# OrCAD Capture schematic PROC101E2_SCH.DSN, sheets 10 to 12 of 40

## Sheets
10 15.EEPROM,PRESENCE DETECT&TEMP: size C; title: EEPROM,PRESENCE DETECTION & TEMP SENSOR
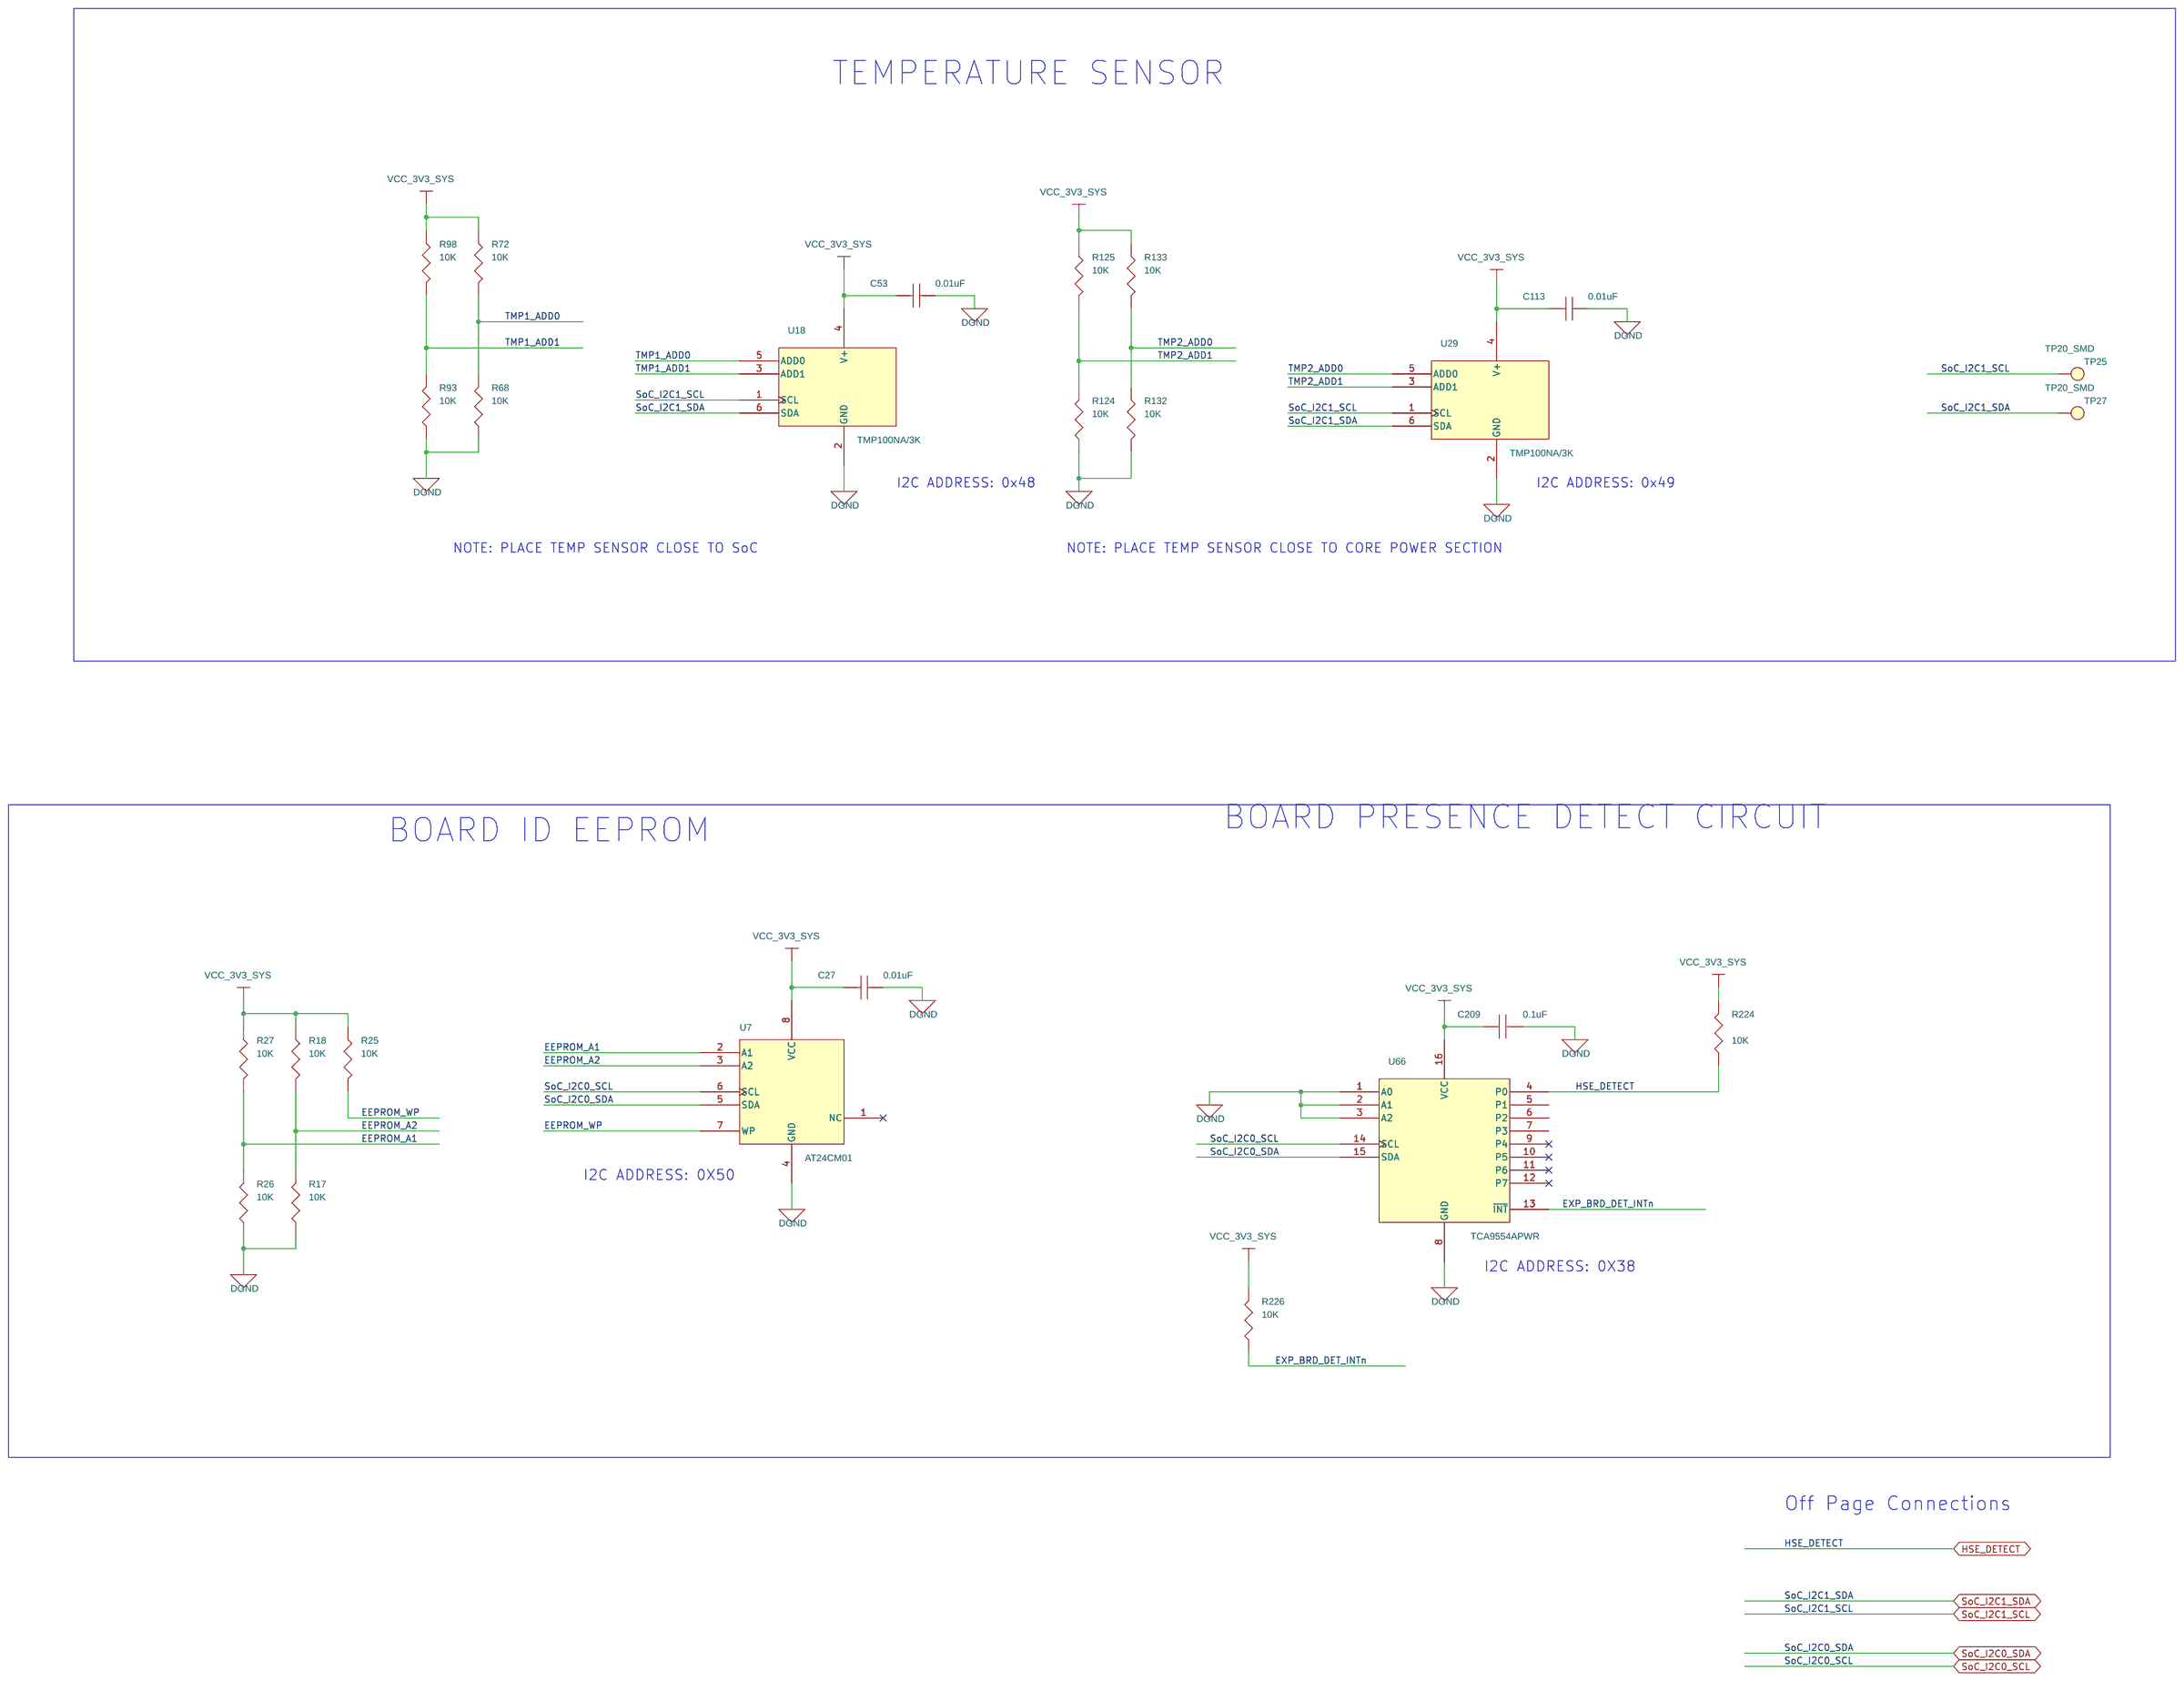
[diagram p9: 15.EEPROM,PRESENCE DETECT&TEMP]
11 31.ETHERNET PHY CLOCK BUFFER: size C; title: ETHERNET PHY CLOCK GENERATOR
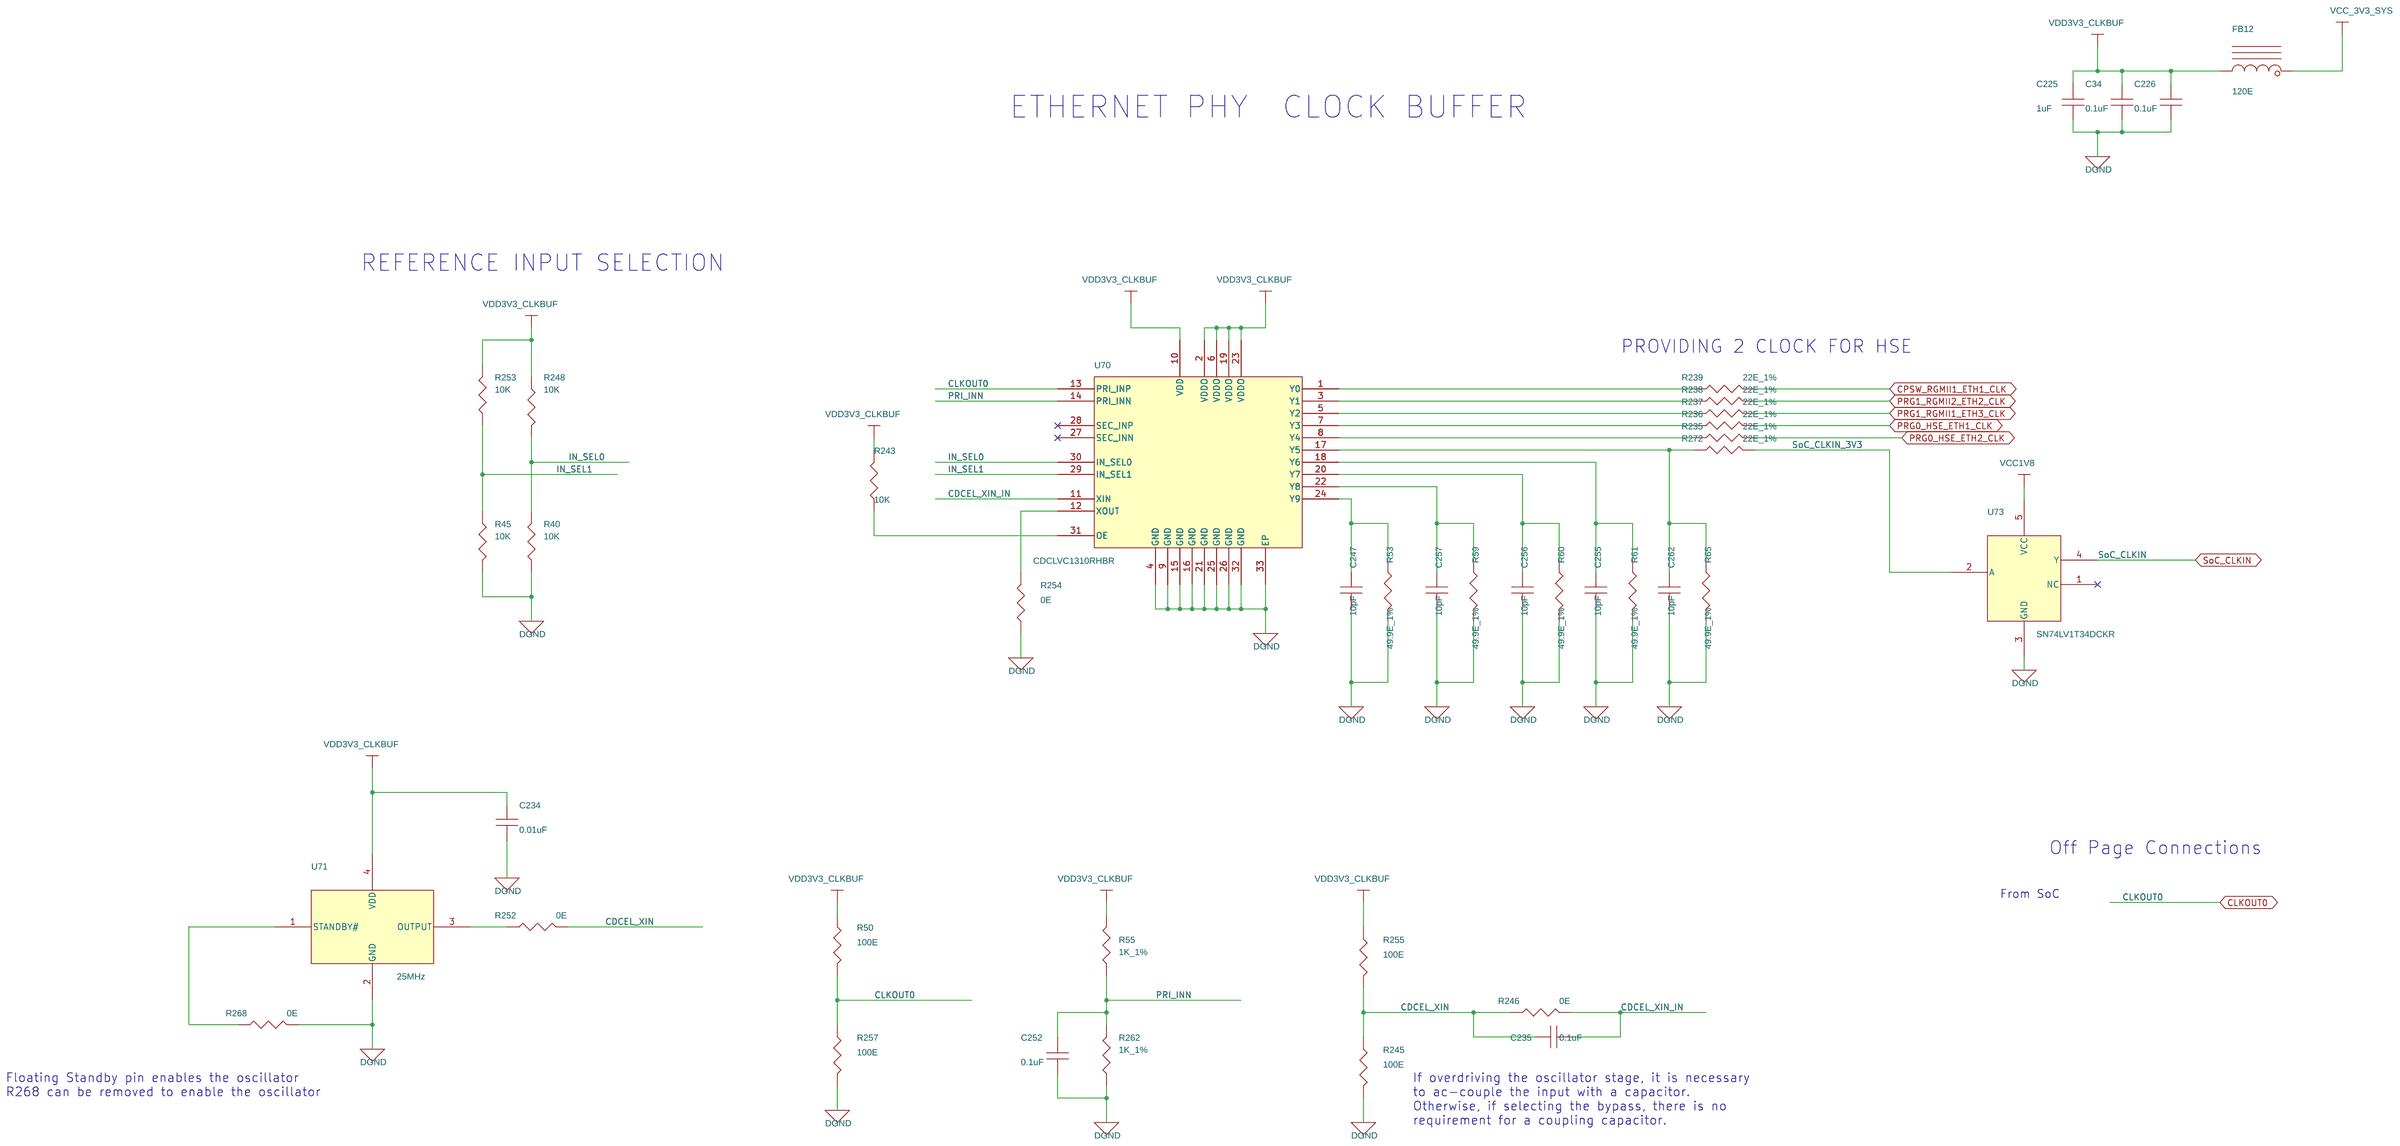
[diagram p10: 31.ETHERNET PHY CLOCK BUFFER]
12 34.MCU GENERAL&SAFETY CONNECTOR: size C; title: MCU GENERAL & SAFETY CONNECTOR
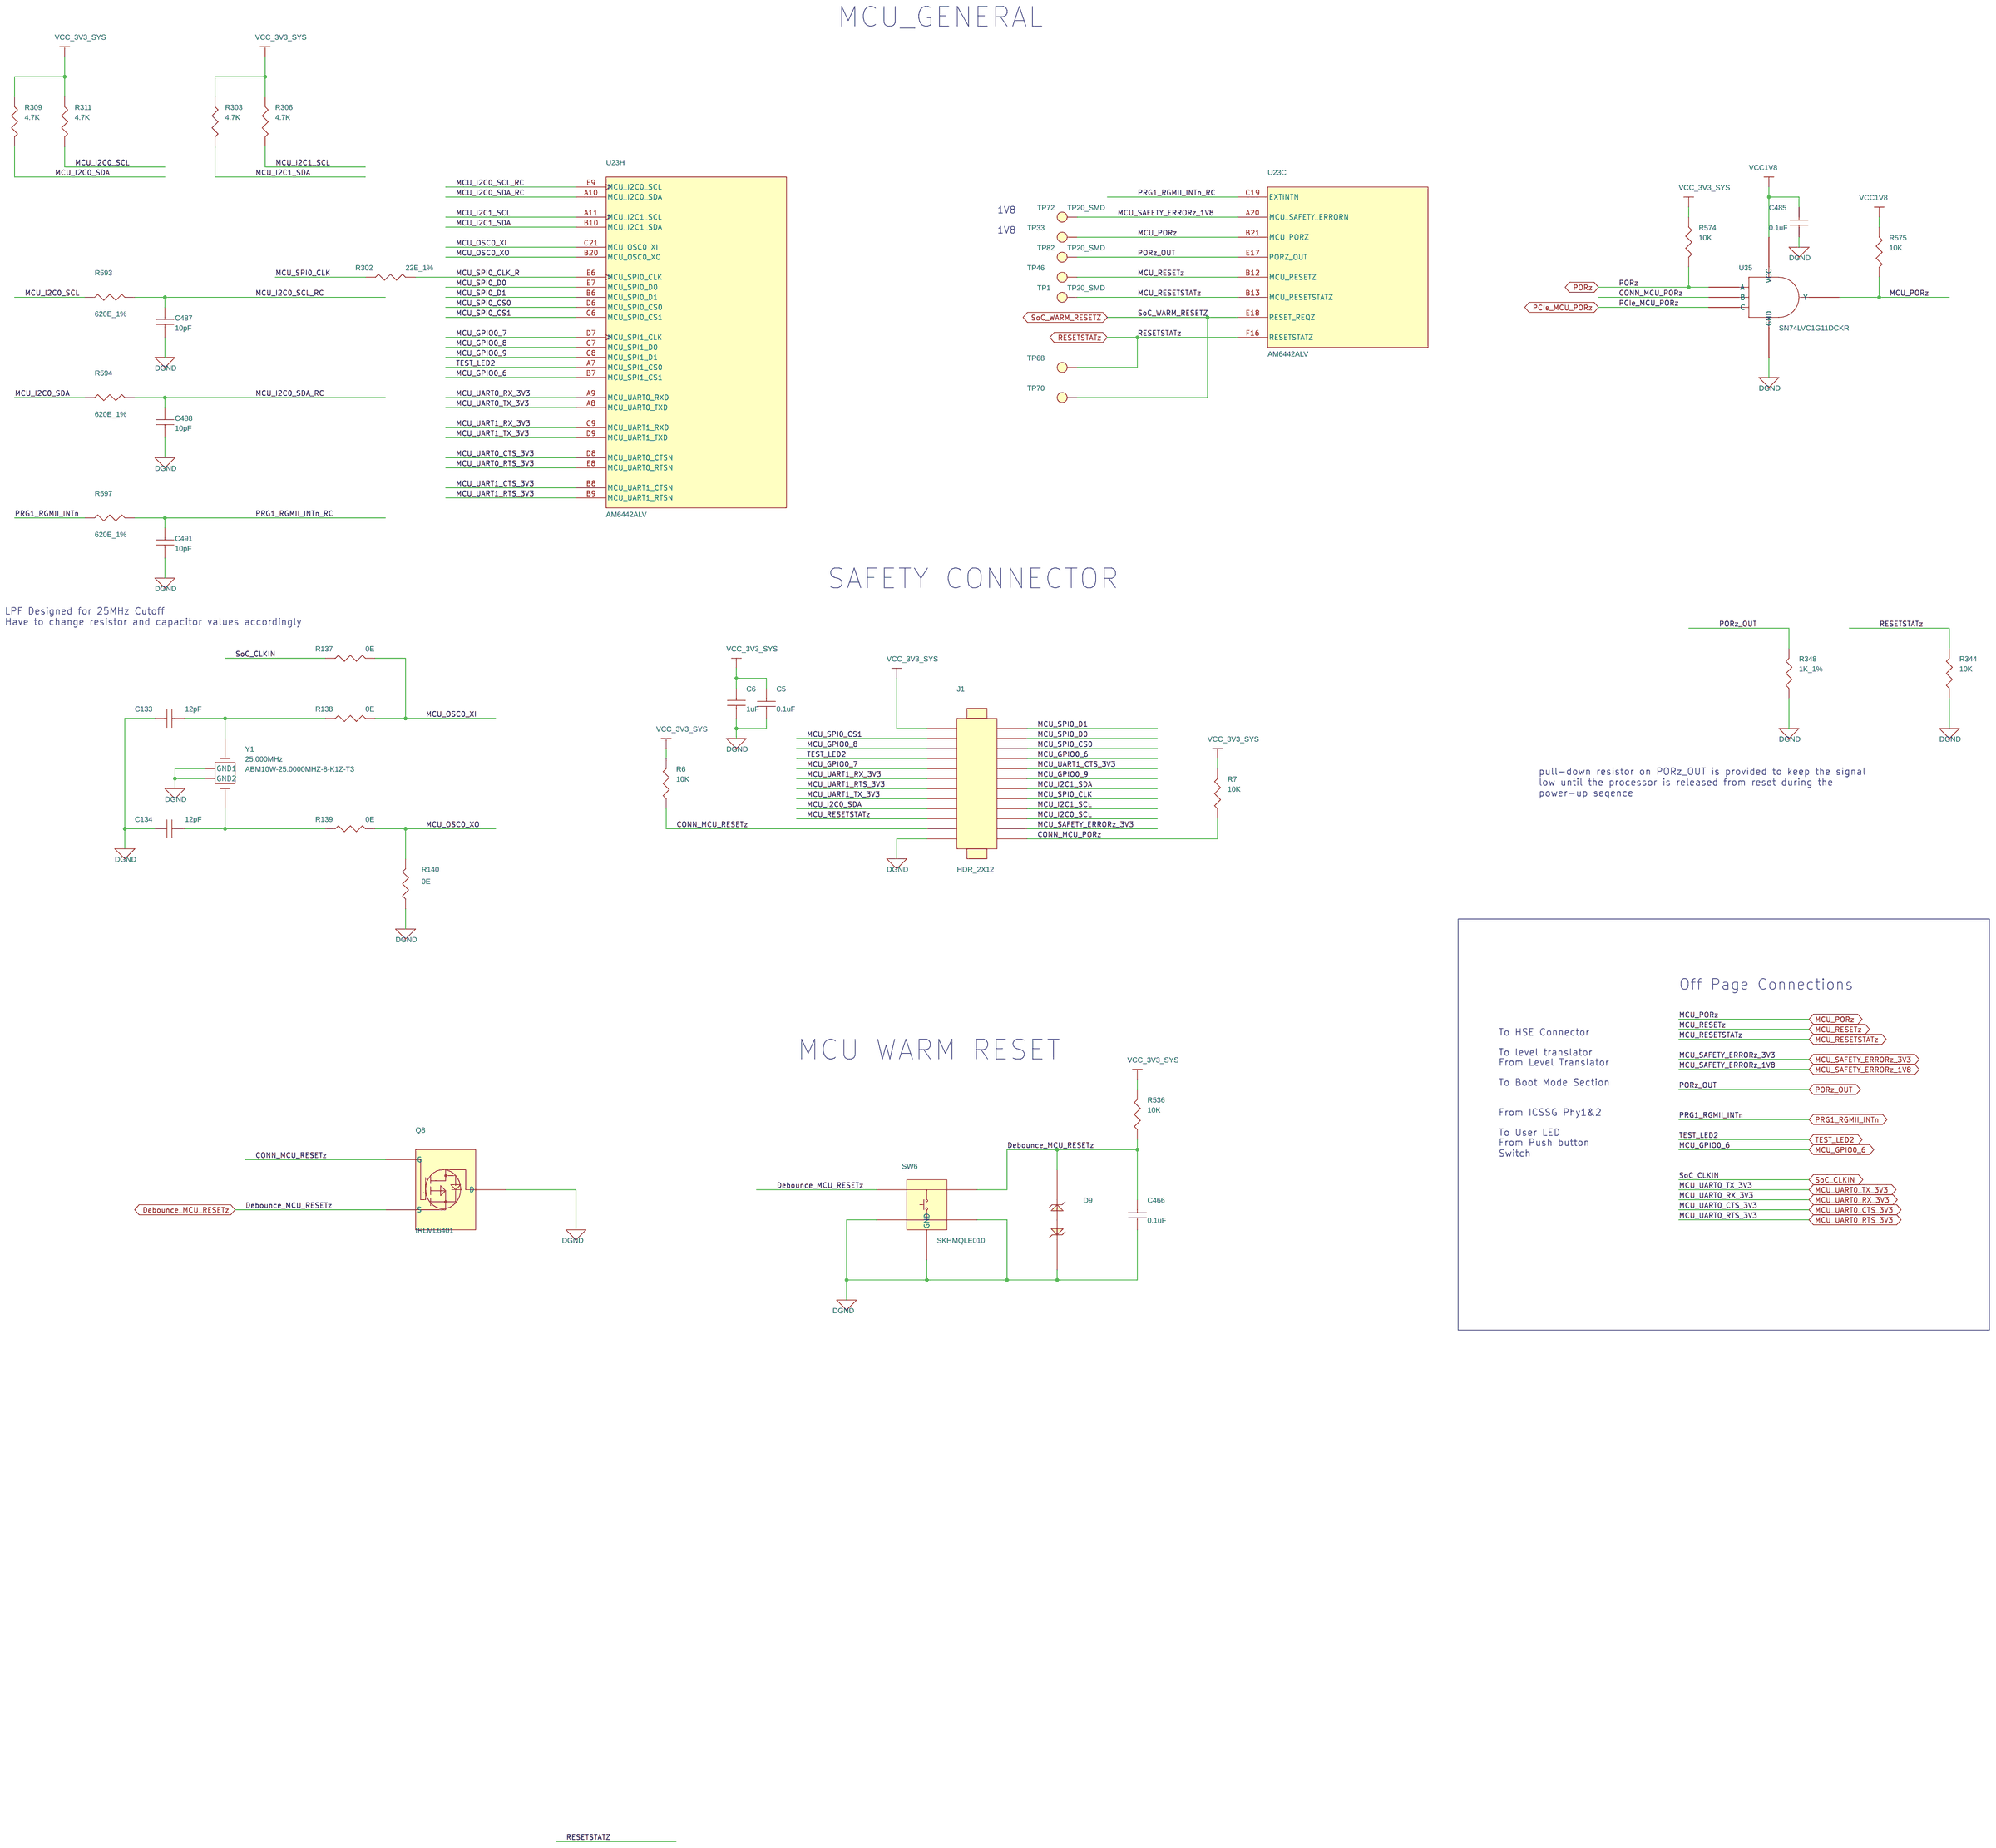
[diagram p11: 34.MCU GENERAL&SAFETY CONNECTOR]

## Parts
sheet 11.SOC VSS
U23  AM6442ALV  [FCBGA441_31-49_680X680_2-6]  (sections A,B,C,D,E,F,G,H,I,J,K,L,M,N,O,P)
sheet 15.EEPROM,PRESENCE DETECT&TEMP
C27  0.01uF  [CAP0402_0-75]
C53  0.01uF  [CAP0402_0-75]
C113  0.01uF  [CAP0402_0-75]
C209  0.1uF  [CAP0402_0-75]
R17  10K  [RES0402_0-5]
R18  10K  [RES0402_0-5]
R25  10K  [RES0402_0-5]
R26  10K  [RES0402_0-5]
R27  10K  [RES0402_0-5]
R68  10K  [RES0402_0-5]
R72  10K  [RES0402_0-5]
R93  10K  [RES0402_0-5]
R98  10K  [RES0402_0-5]
R124  10K  [RES0402_0-5]
R125  10K  [RES0402_0-5]
R132  10K  [RES0402_0-5]
R133  10K  [RES0402_0-5]
R224  10K  [RES0402_0-5]
R226  10K  [RES0402_0-5]
TP25  TP20_SMD  [TP20_SMD]
TP27  TP20_SMD  [TP20_SMD]
U7  AT24CM01  [TSSOP8_25-59_125X180_1-2]
U18  TMP100NA/3K  [SOT23-6_1-5]
U29  TMP100NA/3K  [SOT23-6_1-5]
U66  TCA9554APWR  [TSSOP16_25-59_205X180_1-2]
sheet 31.ETHERNET PHY CLOCK BUFFER
C34  0.1uF  [CAP0402_0-75]
C225  1uF  [CAP0402_0-75]
C226  0.1uF  [CAP0402_0-75]
C234  0.01uF  [CAP0201_0-5]
C235  0.1uF  [CAP0402_0-75]
C247  10pF  [CAP0402_0-75]
C252  0.1uF  [CAP0402_0-75]
C255  10pF  [CAP0402_0-75]
C256  10pF  [CAP0402_0-75]
C257  10pF  [CAP0402_0-75]
C262  10pF  [CAP0402_0-75]
FB12  120E  [IND0603_1]
R40  10K  [RES0402_0-5]
R45  10K  [RES0402_0-5]
R50  100E  [RES0402_0-5]
R53  49.9E_1%  [RES0402_0-5]
R55  1K_1%  [RES0402_0-5]
R59  49.9E_1%  [RES0402_0-5]
R60  49.9E_1%  [RES0402_0-5]
R61  49.9E_1%  [RES0402_0-5]
R65  49.9E_1%  [RES0402_0-5]
R235  22E_1%  [RES0402_0-5]
R236  22E_1%  [RES0402_0-5]
R237  22E_1%  [RES0402_0-5]
R238  22E_1%  [RES0402_0-5]
R239  22E_1%  [RES0402_0-5]
R243  10K  [RES0402_0-5]
R245  100E  [RES0402_0-5]
R246  0E  [RES0402_0-5]
R248  10K  [RES0402_0-5]
R252  0E  [RES0402_0-5]
R253  10K  [RES0402_0-5]
R254  0E  [RES0402_0-5]
R255  100E  [RES0402_0-5]
R257  100E  [RES0402_0-5]
R262  1K_1%  [RES0402_0-5]
R268  0E  [RES0402_0-5]
R272  22E_1%  [RES0402_0-5]
U70  CDCLVC1310RHBR  [QFN32_19-68_200X200_1]
U71  25MHz  [OSC4_ASFLMB_200X130_SMD]
U73  SN74LV1T34DCKR  [SC70-5_1-1]
sheet 34.MCU GENERAL&SAFETY CONNECTOR
C5  0.1uF  [CAP0402_0-75]
C6  1uF  [CAP0402_0-75]
C133  12pF  [CAP0201_0-5]
C134  12pF  [CAP0201_0-5]
C466  0.1uF  [CAP0402_0-75]
C485  0.1uF  [CAP0402_0-75]
C487  10pF  [CAP0402_0-75]
C488  10pF  [CAP0402_0-75]
C491  10pF  [CAP0402_0-75]
D9  TPD1E10B06DPYR  [DIO_DFN0402_0-5]
J1  HDR_2X12  [HDR_2X12_TSW-112-07-D_S_T_8-6]
Q8  IRLML6401  [TO_SOT23-123]
R6  10K  [RES0402_0-5]
R7  10K  [RES0402_0-5]
R137  0E  [RES0402_0-5]
R138  0E  [RES0402_0-5]
R139  0E  [RES0402_0-5]
R140  0E  [RES0402_0-5]
R302  22E_1%  [RES0402_0-5]
R303  4.7K  [RES0402_0-5]
R306  4.7K  [RES0402_0-5]
R309  4.7K  [RES0402_0-5]
R311  4.7K  [RES0402_0-5]
R344  10K  [RES0402_0-5]
R348  1K_1%  [RES0402_0-5]
R536  10K  [RES0402_0-5]
R574  10K  [RES0402_0-5]
R575  10K  [RES0402_0-5]
R593  620E_1%  [RES0402_0-5]
R594  620E_1%  [RES0402_0-5]
R597  620E_1%  [RES0402_0-5]
SW6  SKHMQLE010  [SW4_SKHMQLE010_240X260_SMD_3-1]
TP1  TP20_SMD  [TP20_SMD]
TP33  TP20_SMD  [TP20_SMD]
TP46  TP20_SMD  [TP20_SMD]
TP68  TP20_SMD  [TP20_SMD]
TP70  TP20_SMD  [TP20_SMD]
TP72  TP20_SMD  [TP20_SMD]
TP82  TP20_SMD  [TP20_SMD]
U35  SN74LVC1G11DCKR  [SC70-6]
Y1  25.000MHz  [XTAL4_ABM10W_100X80_SMD_0-6]

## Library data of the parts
U23 = AM64-SVB_BGA441: IC AM64 SoC MICROPROCESSOR BGA441; Chkd/date: MANIRAJA/020520; Crtd /date: ALVY/090420; Custom_Duty: 15%; Customs_HS_Code: 85423100; Distributor_name: NA; Distributor_part_number: NA; Footprint Path: Y:\MIS_DATABASE\Library\ALTIUM_TOOL\PCB_FOOTPRINTS\Altium_Footprint_Lib.PcbLib; Height: 2.57MM; Library Path: Y:\MIS_DATABASE\Library\ALTIUM_TOOL\SCHEMATICS_PARTS\MS_MICROPROCESSOR_Library.schlib; Mfr_name: TEXAS INSTRUMENTS; Mfr_part_number: AM6442ASFGGAALV; Mistral Part No: 141220040002; Package: BGA441; Part_type: ICS\DIGITAL\MICROPROCESSOR; Project: AM64x_SVB BRD; RoHS: NA; Temperature: NA; Tolerance: NA; Voltage: NA; Wattage: NA; Weight: NA; Datasheet: Y:\MIS_DATABASE\DATASHEETS\ICS\DIGITAL\MICROCONTROLLER\AM64-SoC_SVB.PDF
C27 C53 C113 = CAP: CAP CERAMIC 0.01uF 25V 10% X7R 0402; Chkd/date: MANIRAJA/170820; Crtd /date: ALVY/170820; Custom_Duty: 15%; Customs_HS_Code: 85322990; Distributor_name: DIGIKEY; Distributor_part_number: 732-7545-1-ND; Footprint Path: Y:\MIS_DATABASE\Library\ALTIUM_TOOL\PCB_FOOTPRINTS\Altium_Footprint_Lib.PcbLib; Height: 0.55MM; Library Path: Y:\MIS_DATABASE\Library\ALTIUM_TOOL\SCHEMATICS_PARTS\MS_DISCRETE_Library.schlib; Mfr_name: WURTH ELECTRONICS; Mfr_part_number: 885012205050; Mistral Part No: 120011090040-R; Package: 0402; Part_type: CAPACITORS\CERAMIC; Project: AM64x_EVM_BRD; RoHS: RoHS; Temperature: -55°C+125°C; Tolerance: 10%; Voltage: 25V; Wattage: NA; Weight: 0.65mg; Datasheet: Y:\MIS_DATABASE\DATASHEETS\CAPACITORS\885012205050.PDF
C5 C34 C209 C226 C235 C252 C466 C485 = CAP: CAP CERAMIC 0.1uF 25V 20% X5R 0402; Alt_Mfr_name: YAGEO AMERICA; Alt_Mfr_part_number: CC0402KRX5R8BB104; Chkd/date: MANIRAJA/170820; Crtd /date: ALVY/170820; Custom_Duty: 15%; Customs_HS_Code: 85322990; Distributor_name: DIGIKEY; Distributor_part_number: 732-7495-1-ND; Footprint Path: Y:\MIS_DATABASE\Library\ALTIUM_TOOL\PCB_FOOTPRINTS\Altium_Footprint_Lib.PcbLib; Height: 0.55MM; Library Path: Y:\MIS_DATABASE\Library\ALTIUM_TOOL\SCHEMATICS_PARTS\MS_DISCRETE_Library.schlib; Mfr_name: WURTH ELECTRONICS; Mfr_part_number: 885012105018; Mistral Part No: 120020080003-R; Package: 0402; Part_type: CAPACITORS\CERAMIC; Project: AM64x_EVM_BRD; RoHS: RoHS; Temperature: -55°C+85°C; Tolerance: 20%; Voltage: 25V; Wattage: NA; Weight: 0.65mg; Datasheet: Y:\MIS_DATABASE\DATASHEETS\CAPACITORS\885012105018.PDF
R6 R7 R17 R26 R40 R68 R93 R124 R224 R226 R243 R253 R344 R536 = RESISTOR: RES 10K 1/16W 5% 0402; Chkd/date: VASANTHA/061216; Crtd /date: MAZHAR/230805; Custom_Duty: 15%; Customs_HS_Code: 85332119; Distributor_name: DIGIKEY; Distributor_part_number: 311-10KJRCT-ND; Footprint Path: Y:\MIS_DATABASE\Library\ALTIUM_TOOL\PCB_FOOTPRINTS\Altium_Footprint_Lib.PcbLib; Height: 0.40MM; Library Path: Y:\MIS_DATABASE\Library\ALTIUM_TOOL\SCHEMATICS_PARTS\MS_DISCRETE_Library.schlib; Mfr_name: YAGEO AMERICA; Mfr_part_number: RC0402JR-0710KL; Mistral Part No: 110011060021-R; Package: 0402; Part_type: RESISTORS\FIXED; Project: HSE; RoHS: RoHS; Temperature: -55°C+155°C; Tolerance: 5%; Voltage: NA; Wattage: 1/16W; Weight: 0.65mg; Datasheet: Y:\MIS_DATABASE\DATASHEETS\RESISTORS\RCXXXXL-SER_MAR18.PDF
R18 R25 R27 R45 R72 R98 R125 R132 R133 R248 R574 R575 = RESISTOR: RES 10K 1/16W 5% 0402; Assembly: DNI; Chkd/date: VASANTHA/061216; Crtd /date: MAZHAR/230805; Custom_Duty: 15%; Customs_HS_Code: 85332119; Distributor_name: DIGIKEY; Distributor_part_number: 311-10KJRCT-ND; Footprint Path: Y:\MIS_DATABASE\Library\ALTIUM_TOOL\PCB_FOOTPRINTS\Altium_Footprint_Lib.PcbLib; Height: 0.40MM; Library Path: Y:\MIS_DATABASE\Library\ALTIUM_TOOL\SCHEMATICS_PARTS\MS_DISCRETE_Library.schlib; Mfr_name: YAGEO AMERICA; Mfr_part_number: RC0402JR-0710KL; Mistral Part No: 110011060021-R; Package: 0402; Part_type: RESISTORS\FIXED; Project: HSE; RoHS: RoHS; Temperature: -55°C+155°C; Tolerance: 5%; Voltage: NA; Wattage: 1/16W; Weight: 0.65mg; Datasheet: Y:\MIS_DATABASE\DATASHEETS\RESISTORS\RCXXXXL-SER_MAR18.PDF
TP1 TP25 TP27 TP33 TP46 TP68 TP70 TP72 TP82 = TESTPOINT: TESTPOINT CIR 20 SMD; Chkd/date: SHREESHAIL/171006; Crtd /date: MAZHAR/171006; Custom_Duty: NA; Customs_HS_Code: NA; Distributor_name: NA; Distributor_part_number: NA; Footprint Path: Y:\MIS_DATABASE\Library\ALTIUM_TOOL\PCB_FOOTPRINTS\Altium_Footprint_Lib.PcbLib; Height: NA; Library Path: Y:\MIS_DATABASE\Library\ALTIUM_TOOL\SCHEMATICS_PARTS\MS_DISCRETE_Library.schlib; MECHANICAL 3D STEP FILE: NA; Mfr_name: LOCAL; Mistral Part No: NA; Package: SMD; Project: BT MODULE_CSRBC04; RoHS: NA; Temperature: NA; Tolerance: NA; Voltage: NA; Wattage: NA; Weight: NA; Datasheet: NA
U7 = AT24HC04B-TH-B_TSSOP8: IC 1MBIT I2C SERIAL EEPROM TSSOP8; Chkd/date: NAVEED/241114; Crtd /date: VASANTHA/230914; Custom_Duty: 15%; Customs_HS_Code: 85423100; Distributor_name: DIGIKEY; Distributor_part_number: AT24CM01-XHD-TCT-ND; Height: 1.20MM; Mfr_name: ATMEL; Mfr_part_number: AT24CM01-XHD-T; Mistral Part No: 141114090006-R; Package: TSSOP8; Part_type: ICS\DIGITAL\MEMORY; Project: GALILEO_EVM; RoHS: RoHS; Temperature: -40°C+85°C; Tolerance: NA; Voltage: NA; Wattage: NA; Weight: 158mg; Datasheet: Y:\MIS_DATABASE\DATASHEETS\ICS\MEMORY\AT24CM01.PDF
U18 U29 = TMP100NA_3K_SOT23-6: IC TEMPERATURE SENSOR WITH I2C AND SMBUS INTERFACE SOT23-6; Chkd/date: MANIRAJA/290817; Crtd /date: MANIRAJA/290817; Custom_Duty: 15%; Customs_HS_Code: 85423100; Distributor_name: DIGIKEY; Distributor_part_number: 296-26833-1-ND; Height: 1.45MM; Library Ref: TMP100NA/3K_SOT23-6; Mfr_name: TEXAS INSTRUMENTS; Mistral Part No: 141017080030-R; Package: SOT23-6; Part_type: ICS\DIGITAL\PERIPHERAL; Project: TI_MAXIE_CPB; RoHS: RoHS; Temperature: -55°C+125°C; Tolerance: NA; Voltage: NA; Wattage: NA; Weight: 120mg; Datasheet: Y:\MIS_DATABASE\DATASHEETS\ICS\DIGITAL\PERIPHERAL\TMP10XX.PDF
U66 = TCA9554APWR_TSSOP16: IC 8-BIT I2C AND SMBUS I/O EXPANDER WITH INTERRUPT O/P TSSOP16; Chkd/date: MANIRAJA/110917; Crtd /date: MANIRAJA/110917; Custom_Duty: 15%; Customs_HS_Code: 85423100; Distributor_name: DIGIKEY; Distributor_part_number: 296-28120-1-ND; Height: 1.20MM; Mfr_name: TEXAS INSTRUMENTS; Mistral Part No: 141017090007-R; Package: TSSOP16; Part_type: ICS\DIGITAL\BUSTRANSCEIVER; Project: TI_MAXIE_CPB; RoHS: RoHS; Temperature: -40°C+85°C; Tolerance: NA; Voltage: NA; Wattage: NA; Weight: 173mg; Datasheet: Y:\MIS_DATABASE\DATASHEETS\ICS\DIGITAL\BUSTRANSCEIVER\TCA9554.PDF
C6 C225 = CAP: CAP CERAMIC 1uF 10V 20% X5R 0402; Chkd/date: MANIRAJA/210820; Crtd /date: ALVY/190820; Custom_Duty: 15%; Customs_HS_Code: 85322990; Distributor_name: DIGIKEY; Distributor_part_number: 732-7489-1-ND; Footprint Path: Y:\MIS_DATABASE\Library\ALTIUM_TOOL\PCB_FOOTPRINTS\Altium_Footprint_Lib.PcbLib; Height: 0.55MM; Library Path: Y:\MIS_DATABASE\Library\ALTIUM_TOOL\SCHEMATICS_PARTS\MS_DISCRETE_Library.schlib; Mfr_name: WURTH ELECTRONICS; Mfr_part_number: 885012105012; Mistral Part No: 120020080009-R; Package: 0402; Part_type: CAPACITORS\CERAMIC; Project: AM64x_EVM_BRD; RoHS: RoHS; Temperature: -55°C+85°C; Tolerance: 20%; Voltage: 10V; Wattage: NA; Weight: 0.65mg; Datasheet: Y:\MIS_DATABASE\DATASHEETS\CAPACITORS\885012105012.PDF
C234 = CAP: CAP CERAMIC 0.01uF 25V 10% X5R 0201; Chkd/date: MANIRAJA/230118; Crtd /date: MANIRAJA/230118; Custom_Duty: 15%; Customs_HS_Code: 85322990; Distributor_name: DIGIKEY; Distributor_part_number: GRM033R61E103KA12J-ND; Footprint Path: Y:\MIS_DATABASE\Library\ALTIUM_TOOL\PCB_FOOTPRINTS\Altium_Footprint_Lib.PcbLib; Height: 0.33MM; Library Path: Y:\MIS_DATABASE\Library\ALTIUM_TOOL\SCHEMATICS_PARTS\MS_DISCRETE_Library.schlib; Mfr_name: MURATA; Mfr_part_number: GRM033R61E103KA12J; Mistral Part No: 120018010007-R; Package: 0201; Part_type: CAPACITORS\CERAMIC; Project: TI_MAXIE_CPB; RoHS: RoHS; Temperature: -55°C+85°C; Tolerance: 10%; Voltage: 25V; Wattage: NA; Weight: 0.33mg; Datasheet: Y:\MIS_DATABASE\DATASHEETS\CAPACITORS\GRM033R61E103KA12.PDF
C247 C255-C257 = CAP: CAP CERAMIC 10pF 16V 5% C0G(NP0) 0402; Assembly: DNI; Chkd/date: MANIRAJA/100918; Crtd /date: ALVY/100918; Custom_Duty: 15%; Customs_HS_Code: 85322990; Distributor_name: DIGIKEY; Distributor_part_number: 732-7441-1-ND; Footprint Path: Y:\MIS_DATABASE\Library\ALTIUM_TOOL\PCB_FOOTPRINTS\Altium_Footprint_Lib.PcbLib; Height: 0.55MM; Library Path: Y:\MIS_DATABASE\Library\ALTIUM_TOOL\SCHEMATICS_PARTS\MS_DISCRETE_Library.schlib; Mfr_name: WURTH ELECTRONICS; Mfr_part_number: 885012005025; Mistral Part No: 120018030015-R; Package: 0402; Part_type: CAPACITORS\CERAMIC; Project: SMART-M_SCRIPTALK_PB; RoHS: RoHS; Temperature: -55°C+125°C; Tolerance: 5%; Voltage: 16V; Wattage: NA; Weight: 0.65mg; Datasheet: Y:\MIS_DATABASE\DATASHEETS\CAPACITORS\885012005025.PDF
C262 C487 C488 C491 = CAP: CAP CERAMIC 10pF 16V 5% C0G(NP0) 0402; Chkd/date: MANIRAJA/100918; Crtd /date: ALVY/100918; Custom_Duty: 15%; Customs_HS_Code: 85322990; Distributor_name: DIGIKEY; Distributor_part_number: 732-7441-1-ND; Footprint Path: Y:\MIS_DATABASE\Library\ALTIUM_TOOL\PCB_FOOTPRINTS\Altium_Footprint_Lib.PcbLib; Height: 0.55MM; Library Path: Y:\MIS_DATABASE\Library\ALTIUM_TOOL\SCHEMATICS_PARTS\MS_DISCRETE_Library.schlib; Mfr_name: WURTH ELECTRONICS; Mfr_part_number: 885012005025; Mistral Part No: 120018030015-R; Package: 0402; Part_type: CAPACITORS\CERAMIC; Project: SMART-M_SCRIPTALK_PB; RoHS: RoHS; Temperature: -55°C+125°C; Tolerance: 5%; Voltage: 16V; Wattage: NA; Weight: 0.65mg; Datasheet: Y:\MIS_DATABASE\DATASHEETS\CAPACITORS\885012005025.PDF
FB12 = INDUCTOR_FERRITE: IND FERRITE BEAD CHIP 120E 2A 0603; Chkd/date: MANIRAJA/180820; Crtd /date: ALVY/180820; Custom_Duty: 24%; Customs_HS_Code: 85437099; Distributor_name: DIGIKEY; Distributor_part_number: 732-782631141CT-ND; Footprint Path: Y:\MIS_DATABASE\Library\ALTIUM_TOOL\PCB_FOOTPRINTS\Altium_Footprint_Lib.PcbLib; Height: 1.00MM; Library Path: Y:\MIS_DATABASE\Library\ALTIUM_TOOL\SCHEMATICS_PARTS\MS_FILTER_Library.schlib; Mfr_name: WURTH ELECTRONICS; Mfr_part_number: 782631141; Mistral Part No: 130020080015-R; Package: 0603; Part_type: INDUCTOR; Project: AM64x_EVM_BRD; RoHS: RoHS; Temperature: -55°C+125°C; Tolerance: 25%; Voltage: NA; Wattage: NA; Weight: NA; Datasheet: Y:\MIS_DATABASE\DATASHEETS\DISCRETES\INDUCTORS\782631141.PDF
R50 R245 R255 R257 = RESISTOR: RES 100E 1/16W 5% 0402; Chkd/date: MANIRAJA/230817; Crtd /date: MANIRAJA/230817; Custom_Duty: 15%; Customs_HS_Code: 85332119; Distributor_name: DIGIKEY; Distributor_part_number: 541-100JCT-ND; Footprint Path: Y:\MIS_DATABASE\Library\ALTIUM_TOOL\PCB_FOOTPRINTS\Altium_Footprint_Lib.PcbLib; Height: 0.40MM; Library Path: Y:\MIS_DATABASE\Library\ALTIUM_TOOL\SCHEMATICS_PARTS\MS_DISCRETE_Library.schlib; Mfr_name: VISHAY; Mfr_part_number: CRCW0402100RJNED; Mistral Part No: 110014060039-R; Package: 0402; Part_type: RESISTORS\FIXED; Project: TI_MAXIE_CPB; RoHS: RoHS; Temperature: -55°C+155°C; Tolerance: 5%; Voltage: NA; Wattage: 1/16W; Weight: 0.65mg; Datasheet: Y:\MIS_DATABASE\DATASHEETS\RESISTORS\CRCW0603.PDF
R53 R59-R61 = RESISTOR: RES 49.9E 1/16W 1% 0402; Assembly: DNI; Chkd/date: MANIRAJA/210519; Crtd /date: MANIRAJA/210519; Custom_Duty: 15%; Customs_HS_Code: 85332119; Distributor_name: DIGIKEY; Distributor_part_number: 541-3967-1-ND; Footprint Path: Y:\MIS_DATABASE\Library\ALTIUM_TOOL\PCB_FOOTPRINTS\Altium_Footprint_Lib.PcbLib; Height: 0.35MM; Library Path: Y:\MIS_DATABASE\Library\ALTIUM_TOOL\SCHEMATICS_PARTS\MS_DISCRETE_Library.schlib; Mfr_name: VISHAY; Mfr_part_number: CRCW040249R9FKEDC; Mistral Part No: 110009030846-R; Package: 0402; Part_type: RESISTORS\FIXED; Project: RFSU_RFTJ_CARD; RoHS: RoHS; Temperature: -55°C+155°C; Tolerance: 1%; Voltage: NA; Wattage: 1/16W; Weight: 0.65mg; Datasheet: Y:\MIS_DATABASE\DATASHEETS\RESISTORS\CRCW_C-SER.PDF
R55 R262 R348 = RESISTOR: RES 1K 1/10W 1% 0402; Chkd/date: VASANTHA/281216; Crtd /date: MAZHAR/150506; Custom_Duty: 15%; Customs_HS_Code: 85332119; Distributor_name: DIGIKEY; Distributor_part_number: P1.00KLCT-ND; Footprint Path: Y:\MIS_DATABASE\Library\ALTIUM_TOOL\PCB_FOOTPRINTS\Altium_Footprint_Lib.PcbLib; Height: 0.40MM; Library Path: Y:\MIS_DATABASE\Library\ALTIUM_TOOL\SCHEMATICS_PARTS\MS_DISCRETE_Library.schlib; Mfr_name: PANASONIC-ECG; Mfr_part_number: ERJ-2RKF1001X; Mistral Part No: 110009030411-R; Package: 0402; Part_type: RESISTORS\FIXED; Project: VOCERA; RoHS: RoHS; Temperature: -55°C+155°C; Tolerance: 1%; Voltage: NA; Wattage: 1/10W; Weight: 0.8mg; Datasheet: Y:\MIS_DATABASE\DATASHEETS\RESISTORS\PAN-ERJSER_NOV17.PDF
R65 = RESISTOR: RES 49.9E 1/16W 1% 0402; Chkd/date: MANIRAJA/210519; Crtd /date: MANIRAJA/210519; Custom_Duty: 15%; Customs_HS_Code: 85332119; Distributor_name: DIGIKEY; Distributor_part_number: 541-3967-1-ND; Footprint Path: Y:\MIS_DATABASE\Library\ALTIUM_TOOL\PCB_FOOTPRINTS\Altium_Footprint_Lib.PcbLib; Height: 0.35MM; Library Path: Y:\MIS_DATABASE\Library\ALTIUM_TOOL\SCHEMATICS_PARTS\MS_DISCRETE_Library.schlib; Mfr_name: VISHAY; Mfr_part_number: CRCW040249R9FKEDC; Mistral Part No: 110009030846-R; Package: 0402; Part_type: RESISTORS\FIXED; Project: RFSU_RFTJ_CARD; RoHS: RoHS; Temperature: -55°C+155°C; Tolerance: 1%; Voltage: NA; Wattage: 1/16W; Weight: 0.65mg; Datasheet: Y:\MIS_DATABASE\DATASHEETS\RESISTORS\CRCW_C-SER.PDF
R235-R239 R272 R302 = RESISTOR: RES 22E 1/16W 1% 0402; Chkd/date: SUHAS/290910; Crtd /date: MAZHAR/090909; Cust_part_number: 4700-80047E; Custom_Duty: 15%; Customs_HS_Code: 85332119; Distributor_name: DIGIKEY; Distributor_part_number: 311-22.0LRCT-ND; Footprint Path: Y:\MIS_DATABASE\Library\ALTIUM_TOOL\PCB_FOOTPRINTS\Altium_Footprint_Lib.PcbLib; Height: 0.40MM; Library Path: Y:\MIS_DATABASE\Library\ALTIUM_TOOL\SCHEMATICS_PARTS\MS_DISCRETE_Library.schlib; Mfr_name: YAGEO AMERICA; Mfr_part_number: RC0402FR-0722RL; Mistral Part No: 110009090004-R; Package: 0402; Part_type: RESISTORS\FIXED; Project: VMEFMCD; RoHS: RoHS; SIGNAL_MODEL: RESISTOR_RES0402_22E_22E; Temperature: -55°C+155°C; Tolerance: 1%; Voltage: NA; Wattage: 1/16W; Weight: 0.65mg; Datasheet: Y:\MIS_DATABASE\DATASHEETS\RESISTORS\RCXXXXL-SER_MAR18.PDF
R138 R139 R246 R254 R268 = RESISTOR: RES 0E 1/16W JUMPER 0402; Assembly: DNI; Chkd/date: VASANTHA/201216; Crtd /date: MUDDU/190810; Custom_Duty: 15%; Customs_HS_Code: 85332119; Distributor_name: DIGIKEY; Distributor_part_number: 541-0.0JCT-ND; Footprint Path: Y:\MIS_DATABASE\Library\ALTIUM_TOOL\PCB_FOOTPRINTS\Altium_Footprint_Lib.PcbLib; Height: 0.40MM; Library Path: Y:\MIS_DATABASE\Library\ALTIUM_TOOL\SCHEMATICS_PARTS\MS_DISCRETE_Library.schlib; Mfr_name: VISHAY; Mfr_part_number: CRCW04020000Z0ED; Mistral Part No: 110010080019-R; Package: 0402; Part_type: RESISTORS\FIXED; Project: PB_BUGBASE; RoHS: RoHS; Temperature: -55°C+155°C; Tolerance: NA; Voltage: NA; Wattage: 1/16W; Weight: 0.65mg; Datasheet: Y:\MIS_DATABASE\DATASHEETS\RESISTORS\CRCW0603.PDF
R137 R140 R252 = RESISTOR: RES 0E 1/16W JUMPER 0402; Chkd/date: VASANTHA/201216; Crtd /date: MUDDU/190810; Custom_Duty: 15%; Customs_HS_Code: 85332119; Distributor_name: DIGIKEY; Distributor_part_number: 541-0.0JCT-ND; Footprint Path: Y:\MIS_DATABASE\Library\ALTIUM_TOOL\PCB_FOOTPRINTS\Altium_Footprint_Lib.PcbLib; Height: 0.40MM; Library Path: Y:\MIS_DATABASE\Library\ALTIUM_TOOL\SCHEMATICS_PARTS\MS_DISCRETE_Library.schlib; Mfr_name: VISHAY; Mfr_part_number: CRCW04020000Z0ED; Mistral Part No: 110010080019-R; Package: 0402; Part_type: RESISTORS\FIXED; Project: PB_BUGBASE; RoHS: RoHS; Temperature: -55°C+155°C; Tolerance: NA; Voltage: NA; Wattage: 1/16W; Weight: 0.65mg; Datasheet: Y:\MIS_DATABASE\DATASHEETS\RESISTORS\CRCW0603.PDF
U70 = CDCLVC1310RHBR_VQFN32: IC LOW JITTER,LOW POWER CLK BUFFER LEVEL TRANSLATOR VQFN32; Chkd/date: MANIRAJA/061017; Crtd /date: MANIRAJA/061017; Custom_Duty: 15%; Customs_HS_Code: 85423100; Distributor_name: DIGIKEY; Distributor_part_number: 296-30105-1-ND; Height: 1.00MM; Mfr_name: TEXAS INSTRUMENTS; Mistral Part No: 141017100003-R; Package: VQFN32; Part_type: ICS\INTERFACE\LEVEL TRANSLATOR; Project: TI_MAXIE_CPB; RoHS: RoHS; Temperature: -40°C+85°C; Tolerance: NA; Voltage: NA; Wattage: NA; Weight: 72.2mg; Datasheet: Y:\MIS_DATABASE\DATASHEETS\ICS\INTERFACE\CDCLVC1310RHBR.PDF
U71 = OSC_ASFLMB_SMD4: OSC 25MHz 15pF SMD; Chkd/date: USMAN/231113; Crtd /date: USMAN/231113; Custom_Duty: 24%; Customs_HS_Code: 85437099; Distributor_name: DIGIKEY; Distributor_part_number: 535-11025-1-ND; Height: 0.90MM; Mfr_name: ABRACON CORPORATION; Mfr_part_number: ASFLMB-25.000MHZ-LY-T; Mistral Part No: 130013110024-R; Package: SMD; Part_type: OSCILLATORS; Project: DMP; RoHS: RoHS; Temperature: -40°C+85°C; Tolerance: NA; Voltage: NA; Wattage: NA; Weight: NA; Datasheet: Y:\MIS_DATABASE\DATASHEETS\MISC\CRY_OSC\ASFLMB.PDF
U73 = SN74LVC1G07DBVR_SOT23-5: IC SINGLE BUFFER GATE CMOS LOGIC LEVEL SHIFTER SC70-5; Chkd/date: MANIRAJA/130819; Crtd /date: MANIRAJA/130819; Custom_Duty: 15%; Customs_HS_Code: 85423100; Distributor_name: DIGIKEY; Distributor_part_number: 296-37177-1-ND; Footprint Path: Y:\MIS_DATABASE\Library\ALTIUM_TOOL\PCB_FOOTPRINTS\Altium_Footprint_Lib.PcbLib; Height: 1.10MM; Library Path: Y:\MIS_DATABASE\Library\ALTIUM_TOOL\SCHEMATICS_PARTS\MS_GATE_Library.schlib; Mfr_name: TEXAS INSTRUMENTS; Mistral Part No: 141019080005-R; Package: SC70-5; Part_type: ICS\DIGITAL\GATES; Project: BRUKER_SD820_COMMONDO; RoHS: RoHS; Temperature: -40°C+125°C; Tolerance: NA; Voltage: NA; Wattage: NA; Weight: 20mg; Datasheet: Y:\MIS_DATABASE\DATASHEETS\ICS\DIGITAL\GATES\SN74LV1T34.PDF
C133 C134 = CAP: CAP CERAMIC 12pF 25V 5% C0G(NP0) 0201; Chkd/date: MANIRAJA/020620; Crtd /date: ALVY/300520; Custom_Duty: 15%; Customs_HS_Code: 85322990; Distributor_name: DIGIKEY; Distributor_part_number: 490-3144-1-ND; Footprint Path: Y:\MIS_DATABASE\Library\ALTIUM_TOOL\PCB_FOOTPRINTS\Altium_Footprint_Lib.PcbLib; Height: 0.33MM; Library Path: Y:\MIS_DATABASE\Library\ALTIUM_TOOL\SCHEMATICS_PARTS\MS_DISCRETE_Library.schlib; Mfr_name: MURATA; Mfr_part_number: GRM0335C1E120JA01D; Mistral Part No: 120009030213-R; Package: 0201; Part_type: CAPACITORS\CERAMIC; Project: QCS610_NANOSOM; RoHS: RoHS; Temperature: -55°C+125°C; Tolerance: 5%; Voltage: 25V; Wattage: NA; Weight: 0.33mg; Datasheet: Y:\MIS_DATABASE\DATASHEETS\CAPACITORS\GRM0335C1E120JA01.PDF
D9 = DIODE_SOD323: DIODE 1CH ESD PROTECTION X1SON2; Chkd/date: MANIRAJA/040420; Crtd /date: VASANTHA/181114; Custom_Duty: 15%; Customs_HS_Code: 85423100; Distributor_name: DIGIKEY; Distributor_part_number: 296-30406-1-ND; Footprint Path: Y:\MIS_DATABASE\Library\ALTIUM_TOOL\PCB_FOOTPRINTS\Altium_Footprint_Lib.PcbLib; Height: 0.45MM; Library Path: Y:\MIS_DATABASE\Library\ALTIUM_TOOL\SCHEMATICS_PARTS\MS_DISCRETE_Library.schlib; Mfr_name: TEXAS INSTRUMENTS; Mistral Part No: 130014110022-R; Package: X1SON2; Part_type: DIODE; Project: GALILEO_EVM; RoHS: RoHS; Temperature: -40°C+125°C; Tolerance: NA; Voltage: NA; Wattage: NA; Weight: 1mg; Datasheet: Y:\MIS_DATABASE\DATASHEETS\ICS\INTERFACE\TPD1E10B06-SER.PDF
J1 = HEADER_12X2: CON HDR 2X12 2.54MM PITCH ST TH; Chkd/date: MANIRAJA/250420; Crtd /date: ALVY/240420; Custom_Duty: 24%; Customs_HS_Code: 85369090; Distributor_name: DIGIKEY; Distributor_part_number: SAM1032-12-ND; Footprint Path: Y:\MIS_DATABASE\Library\ALTIUM_TOOL\PCB_FOOTPRINTS\Altium_Footprint_Lib.PcbLib; Height: 8.58MM; Library Path: Y:\MIS_DATABASE\Library\ALTIUM_TOOL\SCHEMATICS_PARTS\MS_CONNECTOR_Library.schlib; Mfr_name: SAMTEC; Mfr_part_number: TSW-112-07-S-D; Mistral Part No: 150020040027-R; Package: THRU-HOLE; Part_type: CONNECTOR\HEADERS; Project: AM64x-GP_EVM BRD; RoHS: RoHS; Temperature: -55°C+125°C; Tolerance: NA; Voltage: NA; Wattage: NA; Weight: NA; Datasheet: Y:\MIS_DATABASE\DATASHEETS\CONNECTORS\SAM_TSW-SER.PDF
Q8 = MOSFET_IRLML6401TR: TRANSISTOR MOSFET P-CHANNEL SOT23-3; Chkd/date: SHREESHAIL/020206; Crtd /date: MAZHAR/040505; Custom_Duty: 15%; Customs_HS_Code: 85412900; Distributor_name: DIGIKEY; Distributor_part_number: IRLML6401PBFCT-ND; Height: 1.11MM; Mfr_name: IRF; Mfr_part_number: IRLML6401TRPBF; Mistral Part No: 130009031213-P; Package: SOT23-3; Part_type: TRANSISTOR\MOSFET; Project: G4_SVGA; RoHS: Pb-Free; Temperature: -55°C+150°C; Tolerance: NA; Voltage: NA; Wattage: NA; Weight: NA; Datasheet: Y:\MIS_DATABASE\DATASHEETS\DISCRETES\TRANSISTORS_FETS\IRLML6401.PDF
R303 R306 R309 R311 = RESISTOR: RES 4.7K 1/16W 5% 0402; Chkd/date: VASANTHA/130516; Crtd /date: VASANTHA/130516; Custom_Duty: 15%; Customs_HS_Code: 85332119; Distributor_name: DIGIKEY; Distributor_part_number: 311-4.7KJRCT-ND; Footprint Path: Y:\MIS_DATABASE\Library\ALTIUM_TOOL\PCB_FOOTPRINTS\Altium_Footprint_Lib.PcbLib; Height: 0.40MM; Library Path: Y:\MIS_DATABASE\Library\ALTIUM_TOOL\SCHEMATICS_PARTS\MS_DISCRETE_Library.schlib; Mfr_name: YAGEO AMERICA; Mfr_part_number: RC0402JR-074K7L; Mistral Part No: 110011060001-R; Package: 0402; Part_type: RESISTORS\FIXED; Project: TMDXCSK368; RoHS: RoHS; Temperature: -55°C+155°C; Tolerance: 5%; Voltage: NA; Wattage: 1/16W; Weight: 0.65mg; Datasheet: Y:\MIS_DATABASE\DATASHEETS\RESISTORS\RCXXXXL-SER_MAR18.PDF
R593 R594 R597 = RESISTOR: RES 620E 1/10W 1% 0402; Chkd/date: USMAN/120313; Crtd /date: CHAITHANYA/270912; Custom_Duty: 15%; Customs_HS_Code: 85332119; Distributor_name: DIGIKEY; Distributor_part_number: P620LCT-ND; Footprint Path: Y:\MIS_DATABASE\Library\ALTIUM_TOOL\PCB_FOOTPRINTS\Altium_Footprint_Lib.PcbLib; Height: 0.40MM; Library Path: Y:\MIS_DATABASE\Library\ALTIUM_TOOL\SCHEMATICS_PARTS\MS_DISCRETE_Library.schlib; Mfr_name: PANASONIC-ECG; Mfr_part_number: ERJ-2RKF6200X; Mistral Part No: 110012090013-R; Package: 0402; Part_type: RESISTORS\FIXED; Project: ITS-CONTROLER_CARD; RoHS: RoHS; Temperature: -55°C+155°C; Tolerance: 1%; Voltage: NA; Wattage: 1/10W; Weight: 0.8mg; Datasheet: Y:\MIS_DATABASE\DATASHEETS\RESISTORS\PAN-ERJSER_NOV17.PDF
SW6 = SW4_SKHUPLE010: SWITCH TACTILE SPST ST SMD; Chkd/date: MANIRAJA/051017; Crtd /date: MANIRAJA/051017; Custom_Duty: 24%; Customs_HS_Code: 85369090; Distributor_name: MOUSER; Distributor_part_number: 688-SKHMQLE010; Height: 3.10MM; Mfr_name: ALPS; Mistral Part No: 130017100007-R; Package: SMD; Part_type: ELECTRO-MECHANICAL\SWITCH; Project: TI_MAXIE_CPB; RoHS: RoHS; Temperature: -30°C+85°C; Tolerance: NA; Voltage: NA; Wattage: NA; Weight: NA; Datasheet: Y:\MIS_DATABASE\DATASHEETS\MISC\SWITCHES\SKHMQLE010.PDF
U35 = SN74LVC1G11DCKR_SC70-6: IC SINGLE 3-INPUT POSITIVE-AND GATE SC70-6; Chkd/date: SHREESHAIL/220506; Crtd /date: MAZHAR/150506; Custom_Duty: 15%; Customs_HS_Code: 85423100; Distributor_name: DIGIKEY; Distributor_part_number: 296-18066-1-ND; Height: 1.10MM; Mfr_name: TEXAS INSTRUMENTS; Mistral Part No: 141009030230-R; Part_type: ICS\DIGITAL\GATES; Project: VOCERA; RoHS: Sb/ Br FREE; Datasheet: Y:\MIS_DATABASE\DATASHEETS\ICS\DIGITAL\GATES\SN74LVC1G.PDF
Y1 = CRY4_ABM8G: CRY 25.000MHz 8pF SMD; Chkd/date: MANIRAJA/250620; Crtd /date: ALVY/250620; Custom_Duty: 24%; Customs_HS_Code: 85439000; Distributor_name: DIGIKEY; Distributor_part_number: 535-13736-1-ND; Footprint Path: Y:\MIS_DATABASE\Library\ALTIUM_TOOL\PCB_FOOTPRINTS\Altium_Footprint_Lib.PcbLib; Height: 0.60MM; Library Path: Y:\MIS_DATABASE\Library\ALTIUM_TOOL\SCHEMATICS_PARTS\MS_DISCRETE_Library.schlib; Mfr_name: ABRACON CORPORATION; Mfr_part_number: ABM10W-25.0000MHZ-8-K1Z-T3; Mistral Part No: 130020060044-R; Package: SMD; Part_type: CRYSTAL; Project: AM64x_SVB DUT BRD; RoHS: RoHS; Temperature: -40°C+125°C; Tolerance: NA; Voltage: NA; Wattage: NA; Weight: NA; Datasheet: Y:\MIS_DATABASE\DATASHEETS\MISC\CRY_OSC\ABM10W.PDF

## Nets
DGND: C5.1 C6.2 C27.1 C34.1 C53.1 C113.1 C133.1 C134.1 C209.2 C225.1 C226.1 C234.2 C247.2 C252.1 C255.2 C256.2 C257.2 C262.2 C466.1 C485.1 C487.2 C488.2 C491.2 D9.1 J1.23 Q8.3(D) R17.1 R26.1 R40.1 R45.2 R53.2 R59.2 R60.2 R61.2 R65.2 R68.1 R93.1 R124.1 R132.2 R140.1 R245.2 R254.1 R257.2 R262.1 R268.2 R344.1 R348.1 SW6.3 SW6.4 SW6.5(GND) U7.4(GND) U18.2(GND) U29.2(GND) U35.2(GND) U66.1(A0) U66.2(A1) U66.3(A2) U66.8(GND) U70.4(GND) U70.9(GND) U70.15(GND) U70.16(GND) U70.21(GND) U70.25(GND) U70.26(GND) U70.32(GND) U70.33(EP) U71.2(GND) U73.3(GND) Y1.2(GND1) Y1.4(GND2) ; also on sheet 2 3 4 5 6 7 8 9 13 14 15 16 17 18 19 20 21 22 23 24 25 26 27 28 29 30 39 40
VCC1V8: C485.2 R575.1 U35.5(VCC) U73.5(VCC) ; also on sheet 13 14 15 18 21 24
VCC_3V3_SYS: C5.2 C6.1 C27.2 C53.2 C113.2 C209.1 FB12.1 J1.1 R6.2 R7.2 R18.1 R25.1 R27.1 R72.1 R98.1 R125.1 R133.1 R224.2 R226.2 R303.1 R306.1 R309.1 R311.1 R536.2 R574.1 U7.8(VCC) U18.4(V+) U29.4(V+) U66.16(VCC) ; also on sheet 2 5 6 7 8 13 14 15 16 17 18 19 20 21 23 24 25 26 27 29 30 39 40
VDD3V3_CLKBUF: C34.2 C225.2 C226.2 C234.1 FB12.2 R50.1 R55.2 R243.2 R248.1 R253.2 R255.1 U70.2(VDDO) U70.6(VDDO) U70.10(VDD) U70.19(VDDO) U70.23(VDDO) U71.4(VDD)
CDCEL_XIN: C235.2 R245.1 R246.1 R252.2 R255.2
CDCEL_XIN_IN: C235.1 R246.2 U70.11(XIN)
CLKOUT0: R50.2 R257.1 U70.13(PRI_INP) ; also on sheet 6
CONN_MCU_PORz: J1.24 R7.1 U35.3(B)
CONN_MCU_RESETz: J1.21 Q8.1(G) R6.1
CPSW_RGMII1_ETH1_CLK: R239.2 ; also on sheet 2
Debounce_MCU_RESETz: C466.2 D9.2 Q8.2(S) R536.1 SW6.1 SW6.2 ; also on sheet 25
EEPROM_A1: R26.2 R27.2 U7.2(A1)
EEPROM_A2: R17.2 R18.2 U7.3(A2)
EEPROM_WP: R25.2 U7.7(WP)
EXP_BRD_DET_INTn: R226.1 U66.13(~{INT})
HSE_DETECT: R224.1 U66.4(P0) ; also on sheet 18
IN_SEL0: R40.2 R248.2 U70.30(IN_SEL0)
IN_SEL1: R45.1 R253.1 U70.29(IN_SEL1)
MCU_GPIO0_6: J1.8 U23.B7(MCU_SPI1_CS1) ; also on sheet 25
MCU_GPIO0_7: J1.9 U23.D7(MCU_SPI1_CLK)
MCU_GPIO0_8: J1.5 U23.C7(MCU_SPI1_D0)
MCU_GPIO0_9: J1.12 U23.C8(MCU_SPI1_D1)
MCU_I2C0_SCL: J1.20 R311.2 R593.1
MCU_I2C0_SCL_RC: C487.1 R593.2 U23.E9(MCU_I2C0_SCL)
MCU_I2C0_SDA: J1.17 R309.2 R594.1
MCU_I2C0_SDA_RC: C488.1 R594.2 U23.A10(MCU_I2C0_SDA)
MCU_I2C1_SCL: J1.18 R306.2 U23.A11(MCU_I2C1_SCL)
MCU_I2C1_SDA: J1.14 R303.2 U23.B10(MCU_I2C1_SDA)
MCU_OSC0_XI: R137.2 R138.2 U23.C21(MCU_OSC0_XI)
MCU_OSC0_XO: R139.2 R140.2 U23.B20(MCU_OSC0_XO)
MCU_PORz: R575.2 TP33.1(TP) U23.B21(MCU_PORZ) U35.4(Y) ; also on sheet 18
MCU_RESETSTATz: J1.19 TP1.1(TP) U23.B13(MCU_RESETSTATZ) ; also on sheet 18
MCU_RESETz: TP46.1(TP) U23.B12(MCU_RESETZ) ; also on sheet 18 25
MCU_SAFETY_ERRORz_1V8: TP72.1(TP) U23.A20(MCU_SAFETY_ERRORN) ; also on sheet 13
MCU_SAFETY_ERRORz_3V3: J1.22 ; also on sheet 13
MCU_SPI0_CLK: J1.16 R302.1
MCU_SPI0_CLK_R: R302.2 U23.E6(MCU_SPI0_CLK)
MCU_SPI0_CS0: J1.6 U23.D6(MCU_SPI0_CS0)
MCU_SPI0_CS1: J1.3 U23.C6(MCU_SPI0_CS1)
MCU_SPI0_D0: J1.4 U23.E7(MCU_SPI0_D0)
MCU_SPI0_D1: J1.2 U23.B6(MCU_SPI0_D1)
MCU_UART0_CTS_3V3: U23.D8(MCU_UART0_CTSN) ; also on sheet 23
MCU_UART0_RTS_3V3: U23.E8(MCU_UART0_RTSN) ; also on sheet 23
MCU_UART0_RX_3V3: U23.A9(MCU_UART0_RXD) ; also on sheet 23
MCU_UART0_TX_3V3: U23.A8(MCU_UART0_TXD) ; also on sheet 23
MCU_UART1_CTS_3V3: J1.10 U23.B8(MCU_UART1_CTSN)
MCU_UART1_RTS_3V3: J1.13 U23.B9(MCU_UART1_RTSN)
MCU_UART1_RX_3V3: J1.11 U23.C9(MCU_UART1_RXD)
MCU_UART1_TX_3V3: J1.15 U23.D9(MCU_UART1_TXD)
PCIe_MCU_PORz: U35.6(C) ; also on sheet 5
PORz: R574.2 U35.1(A) ; also on sheet 25
PORz_OUT: R348.2 TP82.1(TP) U23.E17(PORZ_OUT) ; also on sheet 2 24 29 39 40
PRG0_HSE_ETH1_CLK: R236.2 ; also on sheet 18
PRG0_HSE_ETH2_CLK: R235.2 ; also on sheet 18
PRG1_RGMII1_ETH3_CLK: R237.2 ; also on sheet 40
PRG1_RGMII2_ETH2_CLK: R238.2 ; also on sheet 39
PRG1_RGMII_INTn: R597.1 ; also on sheet 2 39 40
PRG1_RGMII_INTn_RC: C491.1 R597.2 U23.C19(EXTINTN)
PRI_INN: C252.2 R55.1 R262.2 U70.14(PRI_INN)
RESETSTATz: R344.2 TP68.1(TP) U23.F16(RESETSTATZ) ; also on sheet 5 13 21 24 29
SoC_CLKIN: R137.1 U73.4(Y)
SoC_CLKIN_3V3: R272.2 U73.2(A)
SoC_I2C0_SCL: U7.6(SCL) U66.14(SCL) ; also on sheet 6 13 18
SoC_I2C0_SDA: U7.5(SDA) U66.15(SDA) ; also on sheet 6 13 18
SoC_I2C1_SCL: TP25.1(TP) U18.1(SCL) U29.1(SCL) ; also on sheet 5 6 7 13 14 30
SoC_I2C1_SDA: TP27.1(TP) U18.6(SDA) U29.6(SDA) ; also on sheet 5 6 7 13 14 30
SoC_WARM_RESETZ: TP70.1(TP) U23.E18(RESET_REQZ) ; also on sheet 25
TEST_LED2: J1.7 U23.A7(MCU_SPI1_CS0) ; also on sheet 21
TMP1_ADD0: R68.2 R72.2 U18.5(ADD0)
TMP1_ADD1: R93.2 R98.2 U18.3(ADD1)
TMP2_ADD0: R132.1 R133.2 U29.5(ADD0)
TMP2_ADD1: R124.2 R125.2 U29.3(ADD1)
N16248811: C256.1 R60.1 U70.20(Y7)
N16248833: C255.1 R61.1 U70.18(Y6)
N16248855: C262.1 R65.1 R272.1 U70.17(Y5)
N16248877: R235.1 U70.8(Y4)
N16248899: R236.1 U70.7(Y3)
N16248921: R237.1 U70.5(Y2)
N16248943: R238.1 U70.3(Y1)
N16248965: R239.1 U70.1(Y0)
N18321769: R243.1 U70.31(OE)
N23484157: C247.1 R53.1 U70.24(Y9)
N23484680: C257.1 R59.1 U70.22(Y8)
N25209998: R268.1 U71.1(STANDBY#)
N25526660: R254.2 U70.12(XOUT)
N27030520: R252.1 U71.3(OUTPUT)
N27977097: C133.2 R138.1 Y1.1
N27977103: C134.2 R139.1 Y1.3

Not connected (* = marked no-connect by the designer): U7 1(NC)*; U66 5(P1) 6(P2) 7(P3) 9(P4)* 10(P5)* 11(P6)* 12(P7)*; U70 27(SEC_INN)* 28(SEC_INP)*; U73 1(NC)*

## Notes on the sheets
sheet 10
- TEMPERATURE SENSOR
- I2C ADDRESS: 0x48
- I2C ADDRESS: 0x49
- NOTE: PLACE TEMP SENSOR CLOSE TO SoC
- NOTE: PLACE TEMP SENSOR CLOSE TO CORE POWER SECTION
- BOARD ID EEPROM
- BOARD PRESENCE DETECT CIRCUIT
- I2C ADDRESS: 0X50
- I2C ADDRESS: 0X38
- Off Page Connections
sheet 11
- ETHERNET PHY  CLOCK BUFFER
- REFERENCE INPUT SELECTION
- PROVIDING 2 CLOCK FOR HSE
- Off Page Connections
- From SoC
- Floating Standby pin enables the oscillator
  R268 can be removed to enable the oscillator
- If overdriving the oscillator stage, it is necessary
  to ac-couple the input with a capacitor.
  Otherwise, if selecting the bypass, there is no
  requirement for a coupling capacitor.
sheet 12
- MCU_GENERAL
- 1V8
- 1V8
- SAFETY CONNECTOR
- LPF Designed for 25MHz Cutoff
  Have to change resistor and capacitor values accordingly
- pull-down resistor on PORz_OUT is provided to keep the signal
  low until the processor is released from reset during the
  power-up seqence
- Off Page Connections
- To HSE Connector
- MCU WARM RESET
- To level translator
- From Level Translator
- To Boot Mode Section
- From ICSSG Phy1&2
- To User LED
- From Push button
  Switch
